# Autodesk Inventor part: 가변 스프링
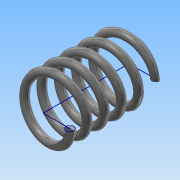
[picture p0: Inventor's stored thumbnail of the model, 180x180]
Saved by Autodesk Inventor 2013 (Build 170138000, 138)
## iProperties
Created: 2019-10
Part Number: 가변 스프링
Material: 스테인리스강
Document SubType Name: Modeling
Designer: Administrator
Density: 8.08 g/cm^3
Mass: 147.816 g
Surface Area: 124.166 cm^2
Volume: 18.294 cm^3
Author: Administrator
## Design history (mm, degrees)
sketch "스케치1"
  geometry: L1 (0, 0)-(21, 0); L2 (0, 0)-(0, 67.25); L3 (0, 67.25)-(21, 67.25); C1 r 3 at (21, 0)
  constraints: 6 end point, 2 perpendicular, 1 centre point, 1 coincident, 1 horizontal
  dimensions: "d0" = 21 distance of L1.start L1.end; "d1" = 67.25 distance of L1.start L2.end (derived); "d2" = 21 distance of L2.end L3.end; "d3" = 6 diameter of C1
feature "코일1" pitch "d4" = 10; turns "d6" = 5; dims "d5" = 67.25 (= d1), "d7" = 0, angle "d8" = 90 deg, angle "d9" = 90 deg, "d10" = 0, "d11" = 0
sketch "스케치2"
  geometry: L1 (0, 25)-(67.25, 25); L2 (67.25, 25)-(67.25, -25); L3 (67.25, -25)-(0, -25); L4 (0, -25)-(0, 25); 2 further points
  constraints: 8 end point, 2 parallel, 1 coincident, 1 horizontal, 1 midpoint, 1 perpendicular
  dimensions: "d12" = 67.25 distance of L1.start L1.end (= d1); "d14" = 50 distance of L1.end L2.end
extrude "돌출1" sketch "스케치2" stored distance "d15" = 0; taper "d16" = 0 deg
node "솔리드1"
